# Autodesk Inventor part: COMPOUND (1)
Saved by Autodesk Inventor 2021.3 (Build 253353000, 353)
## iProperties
Created: 2022-06
Part Number: COMPOUND (1)
Material: Generic
Document SubType Name: Modeling
Designer: Administrator
Density: 1 g/cm^3
Appearance: Default
Title: COMPOUND (1)
Author: Administrator
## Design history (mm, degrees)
feature "Body1"
feature "Body2"
feature "Body3"
feature "Body4"
feature "Body5"
feature "Body6"
feature "Body7"
feature "Body8"
feature "Body9"
feature "Body10"
feature "Body11"
feature "Body12"
feature "Body13"
feature "Body14"
feature "Body15"
feature "Body16"
feature "Body17"
body "Solid1"
body "Solid2"
body "Solid3"
body "Solid4"
body "Solid5"
body "Solid6"
body "Solid7"
body "Solid8"
body "Solid9"
body "Solid10"
body "Solid11"
body "Solid12"
body "Solid13"
body "Solid14"
body "Solid15"
body "Solid16"
body "Solid17"
